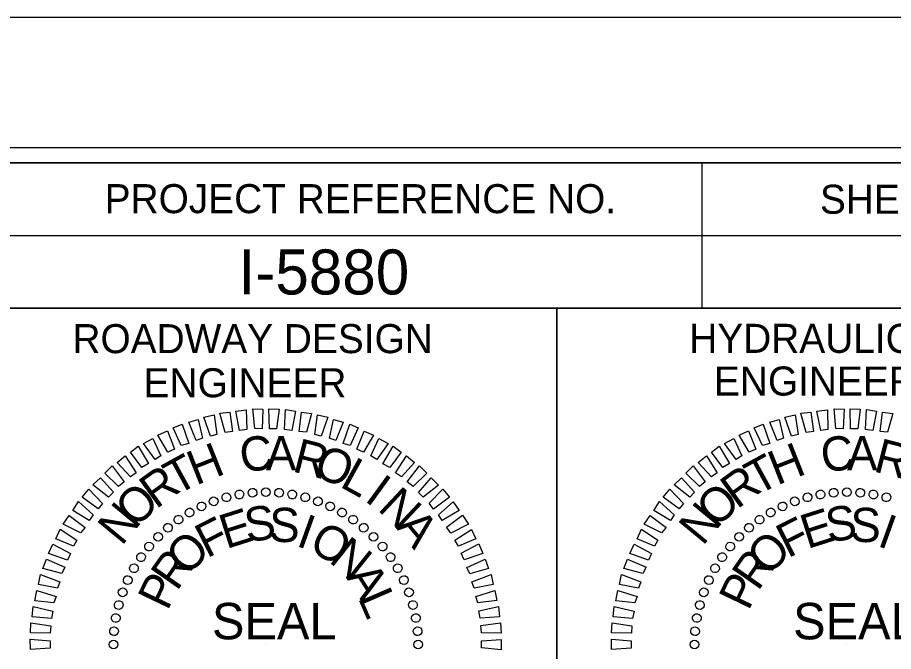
# Model space of a CAD drawing. Extents: x 1648862 to 1650715, y 820691 to 821791.
# Drawn here: x 1650336.4 to 1650487.2, y 821681.9 to 821791 of the extents above; entities that cross this region are included whole.
import ezdxf

# ---------------------------------------------------------------- set-up
doc = ezdxf.new("R2010")
doc.units = 0
for name, color, linetype in [('Old_Level_2', 7, 'Continuous'), ('Sheet Cutting Line CELL', 7, 'Continuous'), ('Sheet Data Field CELL', 7, 'Continuous'), ('Sheet Plot Border Inside CELL', 7, 'Continuous'), ('Sheet Plot Border Outside CELL', 7, 'Continuous'), ('Sheet Profile CELL', 7, 'Continuous'), ('Sheet Profile Grid Major CELL', 7, 'Continuous')]:
    doc.layers.add(name, color=color, linetype=linetype)

msp = doc.modelspace()

# ---------------------------------------------------------------- linework, layer by layer
at = {"layer": 'Old_Level_2'}
for p, q in [((1650372.36, 821708.44), (1650372.36, 821708.44)), ((1650374.65, 821708.89), (1650374.65, 821708.89)), ((1650376.9, 821709.25), (1650376.9, 821709.25)), ((1650379.2, 821709.34), (1650379.2, 821709.34)), ((1650381.5, 821709.22), (1650381.5, 821709.22)), ((1650383.75, 821708.9), (1650383.75, 821708.9)), ((1650385.96, 821708.46), (1650385.96, 821708.46)), ((1650472.41, 821708.44), (1650472.41, 821708.44)), ((1650474.7, 821708.89), (1650474.7, 821708.89)), ((1650476.94, 821709.25), (1650476.94, 821709.25)), ((1650479.24, 821709.34), (1650479.24, 821709.34)), ((1650481.55, 821709.22), (1650481.55, 821709.22)), ((1650483.8, 821708.9), (1650483.8, 821708.9)), ((1650486.01, 821708.46), (1650486.01, 821708.46)), ((1650368.1, 821706.9), (1650368.1, 821706.9)), ((1650370.18, 821707.77), (1650370.18, 821707.77)), ((1650388.17, 821707.77), (1650388.17, 821707.77)), ((1650390.27, 821706.87), (1650390.27, 821706.87)), ((1650468.15, 821706.9), (1650468.15, 821706.9)), ((1650470.22, 821707.77), (1650470.22, 821707.77)), ((1650366.08, 821705.82), (1650366.08, 821705.82)), ((1650392.33, 821705.86), (1650392.33, 821705.86)), ((1650466.13, 821705.82), (1650466.13, 821705.82)), ((1650364.11, 821704.58), (1650364.11, 821704.58)), ((1650394.24, 821704.58), (1650394.24, 821704.58)), ((1650464.16, 821704.58), (1650464.16, 821704.58)), ((1650362.31, 821703.24), (1650362.31, 821703.24)), ((1650396.09, 821703.2), (1650396.09, 821703.2)), ((1650462.35, 821703.24), (1650462.35, 821703.24)), ((1650360.61, 821701.64), (1650360.61, 821701.64)), ((1650397.74, 821701.66), (1650397.74, 821701.66)), ((1650460.66, 821701.64), (1650460.66, 821701.64)), ((1650359.07, 821699.99), (1650359.07, 821699.99)), ((1650399.34, 821699.96), (1650399.34, 821699.96)), ((1650459.12, 821699.99), (1650459.12, 821699.99)), ((1650357.69, 821698.14), (1650357.69, 821698.14)), ((1650400.68, 821698.16), (1650400.68, 821698.16)), ((1650457.74, 821698.14), (1650457.74, 821698.14)), ((1650356.42, 821696.23), (1650356.42, 821696.23)), ((1650401.91, 821696.19), (1650401.91, 821696.19)), ((1650456.46, 821696.23), (1650456.46, 821696.23)), ((1650355.41, 821694.18), (1650355.41, 821694.18)), ((1650402.99, 821694.17), (1650402.99, 821694.17)), ((1650455.45, 821694.18), (1650455.45, 821694.18)), ((1650354.5, 821692.07), (1650354.5, 821692.07)), ((1650403.87, 821692.09), (1650403.87, 821692.09)), ((1650454.55, 821692.07), (1650454.55, 821692.07)), ((1650353.81, 821689.86), (1650353.81, 821689.86)), ((1650404.53, 821689.91), (1650404.53, 821689.91)), ((1650453.85, 821689.86), (1650453.85, 821689.86)), ((1650353.37, 821687.66), (1650353.37, 821687.66)), ((1650404.99, 821687.62), (1650404.99, 821687.62)), ((1650453.42, 821687.66), (1650453.42, 821687.66)), ((1650353.05, 821685.4), (1650353.05, 821685.4)), ((1650405.34, 821685.37), (1650405.34, 821685.37)), ((1650453.1, 821685.4), (1650453.1, 821685.4)), ((1650352.93, 821683.1), (1650352.93, 821683.1)), ((1650379.18, 821683.09), (1650379.18, 821683.09)), ((1650405.44, 821683.07), (1650405.44, 821683.07)), ((1650452.98, 821683.1), (1650452.98, 821683.1)), ((1650479.23, 821683.09), (1650479.23, 821683.09))]:
    msp.add_line(p, q, dxfattribs=at)
for points in [[(1650374.67, 821719.93), (1650374.04, 821723.26), (1650375.81, 821723.5), (1650375.92, 821720.11)], [(1650377.28, 821720.24), (1650376.96, 821723.63), (1650378.69, 821723.61), (1650378.54, 821720.21)], [(1650379.79, 821720.23), (1650379.73, 821723.63), (1650381.46, 821723.6), (1650381.05, 821720.2)], [(1650382.41, 821720.12), (1650382.56, 821723.52), (1650384.29, 821723.23), (1650383.67, 821719.93)], [(1650474.72, 821719.93), (1650474.08, 821723.26), (1650475.86, 821723.5), (1650475.97, 821720.11)], [(1650477.33, 821720.24), (1650477.01, 821723.63), (1650478.73, 821723.61), (1650478.58, 821720.21)], [(1650479.84, 821720.23), (1650479.78, 821723.63), (1650481.5, 821723.6), (1650481.09, 821720.2)], [(1650482.45, 821720.12), (1650482.6, 821723.52), (1650484.34, 821723.23), (1650483.71, 821719.93)], [(1650367.17, 821718.23), (1650365.91, 821721.34), (1650367.53, 821721.84), (1650368.26, 821718.61)], [(1650369.67, 821718.95), (1650368.51, 821722.23), (1650370.28, 821722.62), (1650370.76, 821719.23)], [(1650372.17, 821719.57), (1650371.27, 821722.9), (1650373, 821723.09), (1650373.42, 821719.75)], [(1650384.92, 821719.74), (1650385.34, 821723.1), (1650387.07, 821722.86), (1650386.18, 821719.61)], [(1650387.6, 821719.21), (1650388.06, 821722.62), (1650389.85, 821722.23), (1650388.7, 821718.97)], [(1650390.12, 821718.58), (1650390.85, 821721.83), (1650392.48, 821721.34), (1650391.23, 821718.23)], [(1650467.22, 821718.23), (1650465.96, 821721.34), (1650467.57, 821721.84), (1650468.31, 821718.61)], [(1650469.71, 821718.95), (1650468.56, 821722.23), (1650470.33, 821722.62), (1650470.81, 821719.23)], [(1650472.21, 821719.57), (1650471.32, 821722.9), (1650473.04, 821723.09), (1650473.47, 821719.75)], [(1650484.97, 821719.74), (1650485.38, 821723.1), (1650487.11, 821722.86), (1650486.23, 821719.61)], [(1650364.62, 821717.35), (1650363.21, 821720.36), (1650364.77, 821721.01), (1650365.92, 821717.68)], [(1650392.49, 821717.68), (1650393.64, 821720.99), (1650395.11, 821720.39), (1650393.7, 821717.33)], [(1650464.67, 821717.35), (1650463.26, 821720.36), (1650464.82, 821721.01), (1650465.97, 821717.68)], [(1650362.34, 821716.21), (1650360.62, 821719.11), (1650362.23, 821719.87), (1650363.48, 821716.7)], [(1650394.86, 821716.72), (1650396.11, 821719.83), (1650397.75, 821719.13), (1650396.02, 821716.17)], [(1650462.39, 821716.21), (1650460.66, 821719.11), (1650462.27, 821719.87), (1650463.53, 821716.7)], [(1650357.84, 821713.57), (1650355.86, 821716.2), (1650357.2, 821717.22), (1650358.98, 821714.22)], [(1650360.12, 821714.92), (1650358.13, 821717.71), (1650359.74, 821718.57), (1650361.1, 821715.56)], [(1650397.29, 821715.56), (1650398.65, 821718.57), (1650400.23, 821717.71), (1650398.29, 821714.95)], [(1650399.35, 821714.19), (1650401.13, 821717.25), (1650402.51, 821716.18), (1650400.51, 821713.58)], [(1650457.89, 821713.57), (1650455.9, 821716.2), (1650457.25, 821717.22), (1650459.02, 821714.22)], [(1650460.16, 821714.92), (1650458.18, 821717.71), (1650459.79, 821718.57), (1650461.15, 821715.56)], [(1650355.88, 821711.97), (1650353.59, 821714.44), (1650354.98, 821715.56), (1650356.86, 821712.66)], [(1650401.52, 821712.66), (1650403.41, 821715.57), (1650404.79, 821714.44), (1650402.53, 821711.94)], [(1650455.93, 821711.97), (1650453.63, 821714.44), (1650455.03, 821715.56), (1650456.91, 821712.66)], [(1650353.82, 821710.31), (1650351.48, 821712.57), (1650352.71, 821713.85), (1650354.8, 821711.06)], [(1650403.54, 821711.07), (1650405.63, 821713.83), (1650406.91, 821712.59), (1650404.54, 821710.3)], [(1650453.86, 821710.31), (1650451.52, 821712.57), (1650452.76, 821713.85), (1650454.84, 821711.06)], [(1650352.12, 821708.45), (1650349.42, 821710.55), (1650350.71, 821711.77), (1650352.94, 821709.3)], [(1650405.45, 821709.27), (1650407.66, 821711.77), (1650408.93, 821710.54), (1650406.25, 821708.45)], [(1650452.17, 821708.45), (1650449.47, 821710.55), (1650450.75, 821711.77), (1650452.99, 821709.3)], [(1650350.33, 821706.43), (1650347.57, 821708.42), (1650348.7, 821709.8), (1650351.04, 821707.38)], [(1650407.31, 821707.42), (1650409.68, 821709.82), (1650410.8, 821708.43), (1650408.06, 821706.39)], [(1650450.37, 821706.43), (1650447.62, 821708.42), (1650448.75, 821709.8), (1650451.09, 821707.38)], [(1650348.79, 821704.42), (1650345.94, 821706.14), (1650346.91, 821707.68), (1650349.46, 821705.42)], [(1650408.92, 821705.41), (1650411.44, 821707.65), (1650412.46, 821706.15), (1650409.56, 821704.43)], [(1650448.84, 821704.42), (1650445.99, 821706.14), (1650446.95, 821707.68), (1650449.5, 821705.42)], [(1650347.26, 821702.3), (1650344.31, 821703.81), (1650345.33, 821705.3), (1650348.08, 821703.25)], [(1650410.31, 821703.29), (1650413.05, 821705.33), (1650414.07, 821703.78), (1650411.06, 821702.26)], [(1650447.31, 821702.3), (1650444.35, 821703.81), (1650445.37, 821705.3), (1650448.13, 821703.25)], [(1650346.05, 821700.03), (1650343.04, 821701.28), (1650343.8, 821702.92), (1650346.66, 821701.03)], [(1650411.71, 821701.02), (1650414.61, 821702.9), (1650415.32, 821701.29), (1650412.36, 821700.03)], [(1650446.09, 821700.03), (1650443.09, 821701.28), (1650443.85, 821702.92), (1650446.7, 821701.03)], [(1650345.04, 821697.6), (1650341.78, 821698.75), (1650342.54, 821700.38), (1650345.55, 821698.76)], [(1650412.8, 821698.79), (1650415.86, 821700.41), (1650416.56, 821698.75), (1650413.34, 821697.65)], [(1650445.09, 821697.6), (1650441.83, 821698.75), (1650442.58, 821700.38), (1650445.59, 821698.76)], [(1650344.04, 821695.29), (1650340.78, 821696.17), (1650341.43, 821697.8), (1650344.59, 821696.39)], [(1650413.78, 821696.35), (1650416.95, 821697.76), (1650417.55, 821696.15), (1650414.32, 821695.26)], [(1650444.08, 821695.29), (1650440.83, 821696.17), (1650441.48, 821697.8), (1650444.64, 821696.39)], [(1650343.3, 821692.76), (1650340.04, 821693.39), (1650340.38, 821695.12), (1650343.7, 821693.87)], [(1650414.66, 821693.85), (1650417.99, 821695.11), (1650418.33, 821693.39), (1650415.05, 821692.76)], [(1650443.34, 821692.76), (1650440.09, 821693.39), (1650440.43, 821695.12), (1650443.74, 821693.87)], [(1650342.66, 821690.24), (1650339.41, 821690.6), (1650339.75, 821692.39), (1650343.06, 821691.35)], [(1650415.33, 821691.35), (1650418.61, 821692.4), (1650418.95, 821690.63), (1650415.67, 821690.26)], [(1650442.71, 821690.24), (1650439.46, 821690.6), (1650439.79, 821692.39), (1650443.11, 821691.35)], [(1650342.29, 821687.57), (1650338.94, 821687.82), (1650339.12, 821689.6), (1650342.53, 821688.83)], [(1650415.85, 821688.85), (1650419.23, 821689.64), (1650419.42, 821687.87), (1650416.08, 821687.6)], [(1650442.34, 821687.57), (1650438.99, 821687.82), (1650439.16, 821689.6), (1650442.58, 821688.83)], [(1650342.07, 821685.05), (1650338.67, 821685.1), (1650338.75, 821686.83), (1650342.15, 821686.31)], [(1650416.21, 821686.35), (1650419.6, 821686.82), (1650419.73, 821685.05), (1650416.33, 821685.09)], [(1650442.12, 821685.05), (1650438.72, 821685.1), (1650438.79, 821686.83), (1650442.2, 821686.31)], [(1650342.07, 821682.44), (1650338.67, 821682.22), (1650338.64, 821684), (1650342.04, 821683.69)], [(1650442.11, 821682.44), (1650438.72, 821682.22), (1650438.69, 821684), (1650442.09, 821683.69)], [(1650416.3, 821683.73), (1650419.7, 821683.95), (1650419.73, 821682.17), (1650416.33, 821682.48)]]:
    msp.add_lwpolyline(points, close=True, dxfattribs=at)
for centre, major_axis in [((1650374.63, 821708.92), (-0.131, 0.742)), ((1650376.9, 821709.21), (-0.066, 0.75)), ((1650379.18, 821709.31), (0, 0.753)), ((1650381.47, 821709.21), (0.066, 0.75)), ((1650383.74, 821708.92), (0.131, 0.742)), ((1650474.68, 821708.92), (-0.131, 0.742)), ((1650476.95, 821709.21), (-0.066, 0.75)), ((1650479.23, 821709.31), (0, 0.753)), ((1650481.52, 821709.21), (0.066, 0.75)), ((1650483.79, 821708.92), (0.131, 0.742)), ((1650370.21, 821707.73), (-0.258, 0.708)), ((1650372.4, 821708.42), (-0.195, 0.727)), ((1650385.97, 821708.42), (0.195, 0.727)), ((1650388.15, 821707.73), (0.258, 0.708)), ((1650470.26, 821707.73), (-0.258, 0.708)), ((1650472.44, 821708.42), (-0.195, 0.727)), ((1650486.02, 821708.42), (0.195, 0.727)), ((1650366.07, 821705.8), (-0.376, 0.652)), ((1650368.1, 821706.86), (-0.318, 0.682)), ((1650390.27, 821706.86), (0.318, 0.682)), ((1650392.3, 821705.8), (0.376, 0.652)), ((1650466.12, 821705.8), (-0.376, 0.652)), ((1650468.15, 821706.86), (-0.318, 0.682)), ((1650364.14, 821704.57), (-0.432, 0.617)), ((1650394.23, 821704.57), (0.432, 0.617)), ((1650464.19, 821704.57), (-0.432, 0.617)), ((1650362.33, 821703.18), (-0.484, 0.577)), ((1650396.04, 821703.18), (0.484, 0.577)), ((1650462.37, 821703.18), (-0.484, 0.577)), ((1650360.64, 821701.63), (-0.532, 0.532)), ((1650397.73, 821701.63), (0.532, 0.532)), ((1650460.69, 821701.63), (-0.532, 0.532)), ((1650359.09, 821699.95), (-0.577, 0.484)), ((1650399.28, 821699.95), (0.577, 0.484)), ((1650459.14, 821699.95), (-0.577, 0.484)), ((1650357.7, 821698.13), (-0.617, 0.432)), ((1650400.67, 821698.13), (0.617, 0.432)), ((1650457.75, 821698.13), (-0.617, 0.432)), ((1650356.47, 821696.2), (-0.652, 0.376)), ((1650401.9, 821696.2), (0.652, 0.376)), ((1650456.52, 821696.2), (-0.652, 0.376)), ((1650355.41, 821694.17), (-0.682, 0.318)), ((1650402.95, 821694.17), (0.682, 0.318)), ((1650455.46, 821694.17), (-0.682, 0.318)), ((1650354.54, 821692.06), (-0.708, 0.258)), ((1650403.83, 821692.06), (0.708, 0.258)), ((1650454.59, 821692.06), (-0.708, 0.258)), ((1650353.85, 821689.87), (-0.727, 0.195)), ((1650404.52, 821689.87), (0.727, 0.195)), ((1650453.9, 821689.87), (-0.727, 0.195)), ((1650353.36, 821687.64), (-0.742, 0.131)), ((1650405.01, 821687.64), (0.742, 0.131)), ((1650453.4, 821687.64), (-0.742, 0.131)), ((1650353.06, 821685.37), (-0.75, 0.066)), ((1650405.31, 821685.37), (0.75, 0.066)), ((1650453.1, 821685.37), (-0.75, 0.066)), ((1650352.96, 821683.09), (-0.753, 0)), ((1650405.41, 821683.09), (0.753, 0)), ((1650453, 821683.09), (-0.753, 0))]:
    msp.add_ellipse(centre, major_axis=major_axis, ratio=0.999708, dxfattribs=at)
at = {"layer": 'Sheet Cutting Line CELL'}
msp.add_line((1650546.28, 821791.02), (1648862.28, 821791.02), dxfattribs=at)
at = {"layer": 'Sheet Plot Border Inside CELL'}
msp.add_lwpolyline([(1648875.28, 820713.47), (1650541.78, 820713.47), (1650541.78, 821768.57), (1648875.28, 821768.57)], close=True, dxfattribs=at)
at = {"layer": 'Sheet Plot Border Outside CELL'}
msp.add_lwpolyline([(1648862.28, 820691.02), (1650546.28, 820691.02), (1650546.28, 821791.02), (1648862.28, 821791.02)], close=True, dxfattribs=at)
at = {"layer": 'Sheet Profile CELL'}
for p, q in [((1650454.28, 821765.97), (1650454.28, 821740.97)), ((1650329.23, 821753.47), (1650529.28, 821753.47)), ((1650429.28, 821740.97), (1650429.28, 821628.52))]:
    msp.add_line(p, q, dxfattribs=at)
for points in [[(1650529.28, 821766.02), (1649029.28, 821766.02), (1649029.28, 820716.02), (1650529.28, 820716.02)], [(1650329.23, 821766.02), (1650529.28, 821766.02), (1650529.28, 821740.97), (1650329.23, 821740.97)], [(1650329.23, 821740.97), (1650429.28, 821740.97), (1650429.28, 821628.47), (1650329.23, 821628.47)], [(1650429.28, 821740.97), (1650529.28, 821740.97), (1650529.28, 821628.47), (1650429.28, 821628.47)]]:
    msp.add_lwpolyline(points, close=True, dxfattribs=at)
at = {"layer": 'Sheet Profile Grid Major CELL'}
msp.add_lwpolyline([(1650279.23, 821738.96), (1650279.23, 821266.02), (1650329.23, 821266.02), (1650329.23, 821766.02), (1650355.53, 821766.02)], dxfattribs=at)

# ---------------------------------------------------------------- texts
at = {"layer": 'Old_Level_2'}
for s, rotation, p in [('C', 7.2199, (1650375.06, 821712.67)), ('A', 0.0203, (1650379.18, 821713.05)), ('C', 7.2199, (1650475.11, 821712.67)), ('A', 0.0203, (1650479.23, 821713.05)), ('H', 21.6195, (1650367.15, 821710.44)), ('R', 345.6211, (1650383.58, 821712.92)), ('H', 21.6195, (1650467.2, 821710.44)), ('R', 345.6211, (1650483.63, 821712.92)), ('T', 28.8198, (1650363.78, 821708.65)), ('O', 338.4212, (1650387.1, 821712.2)), ('T', 28.8198, (1650463.83, 821708.65)), ('L', 331.2209, (1650391.73, 821710.34)), ('R', 36.0205, (1650360.27, 821706.29)), ('R', 36.0205, (1650460.31, 821706.29)), ('I', 324.0201, (1650396.01, 821707.91)), ('O', 43.2217, (1650356.72, 821702.99)), ('N', 316.8189, (1650398.29, 821706.33)), ('O', 43.2217, (1650456.76, 821702.99)), ('N', 50.4235, (1650354.36, 821699.91)), ('S', 8.2556, (1650375.95, 821700.65)), ('S', 358.9004, (1650379.71, 821700.77)), ('N', 50.4235, (1650454.41, 821699.91)), ('S', 8.2556, (1650476, 821700.65)), ('S', 358.9004, (1650479.76, 821700.77)), ('F', 26.967, (1650369.04, 821697.87)), ('E', 17.6111, (1650372.36, 821699.49)), ('I', 340.1896, (1650384.22, 821700.12)), ('A', 309.6172, (1650401.42, 821703.29)), ('F', 26.967, (1650469.09, 821697.87)), ('E', 17.6111, (1650472.41, 821699.49)), ('I', 340.1896, (1650484.27, 821700.12)), ('O', 330.8335, (1650386.33, 821699.42)), ('O', 45.6812, (1650365.65, 821694.72)), ('N', 321.4766, (1650389.86, 821697.39)), ('O', 45.6812, (1650465.69, 821694.72)), ('R', 55.0397, (1650363.86, 821692.13)), ('R', 55.0397, (1650463.91, 821692.13)), ('A', 302.7603, (1650392.89, 821694.73)), ('P', 64.3989, (1650362.25, 821688.75)), ('P', 64.3989, (1650462.29, 821688.75)), ('L', 293.4009, (1650394.99, 821691.15))]:
    msp.add_text(s, height=5.9, rotation=rotation, dxfattribs=at).set_placement(p)
for p in [(1650369.91, 821683.97), (1650469.96, 821683.97)]:
    msp.add_text('SEAL', height=6.273, dxfattribs=at).set_placement(p)
at = {"layer": 'Sheet Data Field CELL'}
msp.add_text('I-5880', height=7.75, dxfattribs=at).set_placement((1650374.49, 821743.34))
at = {"layer": 'Sheet Profile CELL'}
for s, height, p in [('PROJECT REFERENCE NO.', 5.0001, (1650351.44, 821757.34)), ('SHEET NO.', 5, (1650474.59, 821757.24)), ('ROADWAY DESIGN', 5.0001, (1650345.89, 821733.24)), ('HYDRAULICS', 5, (1650452.09, 821733.29)), ('ENGINEER', 5, (1650456.34, 821725.94)), ('ENGINEER', 5, (1650358.14, 821725.64))]:
    msp.add_text(s, height=height, dxfattribs=at).set_placement(p)

doc.saveas('drawing.dxf')
